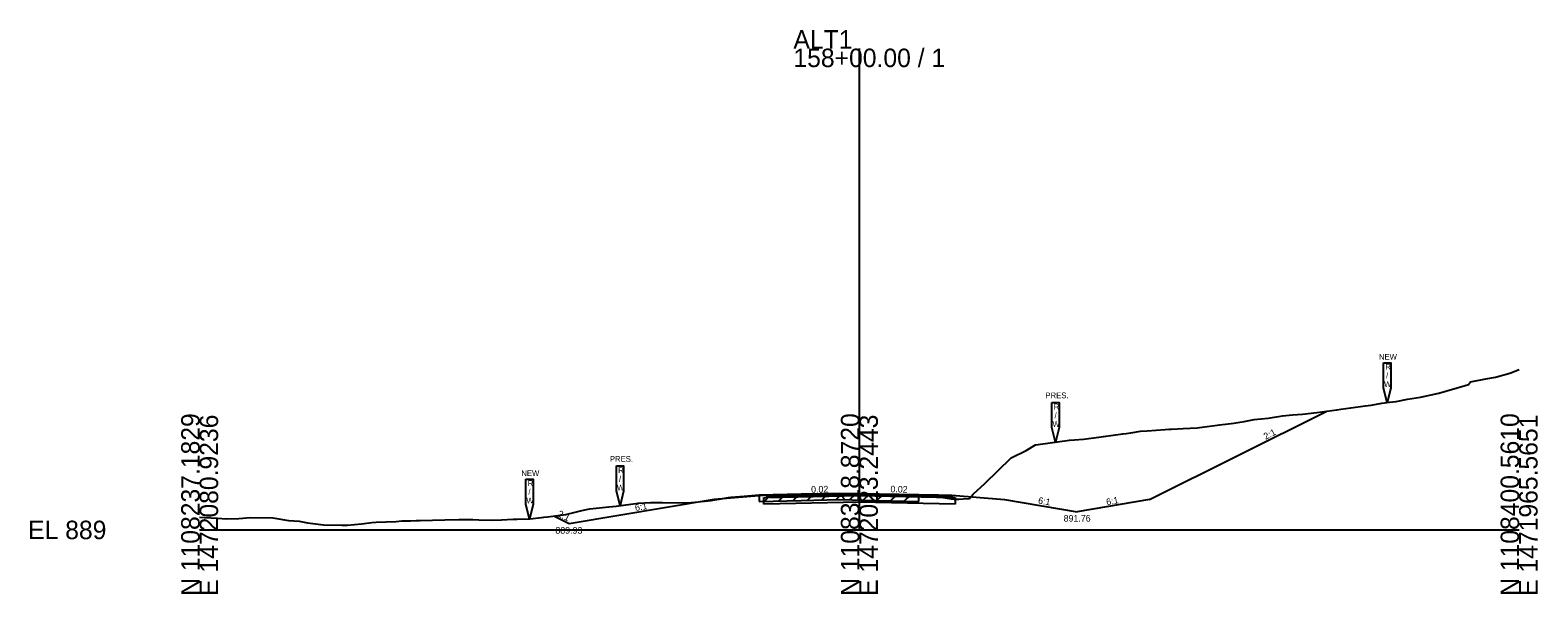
# Model space of a CAD drawing. Extents: x -26 to 2203, y -10 to 19568.
# Drawn here: x 974.3 to 1202.8, y -9.7 to 75.8 of the extents above; entities that cross this region are included whole.
import ezdxf

# ---------------------------------------------------------------- set-up
doc = ezdxf.new("R2010")
doc.units = 0
for name, color, linetype in [('RD_GPK_XS_Cell', 7, 'Continuous'), ('RD_XS_Base', 7, 'Continuous'), ('RD_XS_ExGround', 7, 'Continuous'), ('RD_XS_ExPaveRet', 7, 'Continuous'), ('RD_XS_ExRW', 7, 'Continuous'), ('RD_XS_Greenside', 7, 'Continuous'), ('RD_XS_NewRW', 7, 'Continuous'), ('RD_XS_Pave', 7, 'Continuous'), ('RD_XS_TieSlope', 7, 'Continuous'), ('RD_XS_TX_Slope', 7, 'Continuous')]:
    doc.layers.add(name, color=color, linetype=linetype)

msp = doc.modelspace()

# ---------------------------------------------------------------- linework, layer by layer
at = {"layer": 'RD_GPK_XS_Cell'}
for p, q in [((1100, 0), (1100, 72.98)), ((1000, 0), (1100, 0)), ((1100, 0), (1200, 0))]:
    msp.add_line(p, q, dxfattribs=at)
at = {"layer": 'RD_XS_Base'}
for points in [[(1085.5, 4.93), (1086, 4.94), (1100, 5.22), (1114, 4.94), (1114.5, 4.93)], [(1085.5, 3.93), (1085.5, 4.93)], [(1114.5, 4.93), (1114.5, 3.93)], [(1114.5, 3.93), (1100, 4.22), (1085.5, 3.93)]]:
    msp.add_lwpolyline(points, dxfattribs=at)
at = {"layer": 'RD_XS_ExGround'}
msp.add_lwpolyline([(1000, 1.94), (1000.73, 1.88), (1002.68, 1.79), (1004.06, 1.66), (1005.94, 1.73), (1007.73, 1.89), (1011.09, 1.83), (1011.42, 1.78), (1013.45, 1.42), (1015.08, 1.31), (1016.34, 1.07), (1018.75, 0.79), (1021.54, 0.7), (1022.42, 0.74), (1024.55, 0.94), (1026.1, 1.13), (1026.74, 1.16), (1029.77, 1.28), (1030.67, 1.37), (1031.94, 1.38), (1032.82, 1.42), (1033.44, 1.44), (1037.14, 1.54), (1039.28, 1.6), (1040.79, 1.6), (1041.43, 1.57), (1042.34, 1.51), (1044.46, 1.48), (1045.74, 1.53), (1047.54, 1.61), (1048.13, 1.63), (1050.04, 1.68), (1051.8, 1.86), (1052.19, 1.92), (1052.75, 1.97), (1055.48, 2.33), (1057.95, 2.94), (1058.65, 3.1), (1059.15, 3.19), (1062.03, 3.49), (1063.15, 3.61), (1066.49, 4.07), (1068.35, 4.18), (1069.41, 4.17), (1070.16, 4.18), (1073.84, 4.09), (1074.53, 4.18), (1077.51, 4.46), (1078.02, 4.56), (1078.75, 4.69), (1080.18, 4.92), (1080.55, 4.97), (1082.53, 5.13), (1084.82, 5.31), (1091.16, 5.46), (1097.01, 5.59), (1100, 5.51), (1102.54, 5.45), (1108.96, 5.3), (1110.93, 5.23), (1111.45, 5.14), (1113.89, 4.72), (1114.35, 4.65), (1115.09, 4.65), (1115.75, 4.71), (1116.67, 4.79), (1117.27, 5.43), (1119.01, 7.02), (1123.01, 10.91), (1125.29, 12.04), (1126.69, 12.89), (1127.12, 12.95), (1131.84, 13.63), (1132.6, 13.68), (1133.99, 13.77), (1136.27, 14.06), (1137, 14.16), (1139.94, 14.55), (1140.45, 14.61), (1141.17, 14.73), (1142.6, 14.98), (1143.61, 15.04), (1146.37, 15.22), (1146.91, 15.27), (1147.29, 15.29), (1149.06, 15.4), (1151.21, 15.47), (1151.57, 15.51), (1154.63, 15.92), (1156.77, 16.2), (1157.67, 16.33), (1158.3, 16.45), (1159.82, 16.73), (1161.98, 16.96), (1164.13, 17.29), (1165.65, 17.43), (1167.17, 17.56), (1169.32, 17.8), (1172.37, 18.23), (1172.99, 18.31), (1174.48, 18.51), (1176.67, 18.8), (1177.57, 18.94), (1179.19, 19.22), (1180.34, 19.35), (1181.35, 19.46), (1183.1, 19.84), (1185.07, 20.13), (1187.81, 20.73), (1191.81, 21.91), (1192.31, 22.03), (1192.62, 22.47), (1194.96, 22.9), (1196.42, 23.18), (1198.57, 23.76), (1200, 24.33)], dxfattribs=at)
at = {"layer": 'RD_XS_ExPaveRet'}
for p, q in [((1084.82, 5.31), (1084.82, 4.31)), ((1085.57, 4.33), (1086.59, 5.35)), ((1087.74, 4.38), (1088.77, 5.4)), ((1089.91, 4.43), (1090.94, 5.45)), ((1092.08, 4.48), (1093.11, 5.5)), ((1094.25, 4.53), (1095.28, 5.55)), ((1096.42, 4.58), (1097.43, 5.58)), ((1098.52, 4.55), (1099.5, 5.53)), ((1100.59, 4.5), (1101.57, 5.48)), ((1102.66, 4.45), (1103.64, 5.43)), ((1104.73, 4.4), (1105.71, 5.38)), ((1106.8, 4.35), (1107.78, 5.33)), ((1108.96, 5.3), (1108.96, 4.3)), ((1108.87, 4.3), (1108.96, 4.38))]:
    msp.add_line(p, q, dxfattribs=at)
msp.add_lwpolyline([(1084.82, 4.31), (1091.18, 4.46), (1097, 4.59), (1102.52, 4.45), (1108.96, 4.3)], dxfattribs=at)
at = {"layer": 'RD_XS_ExRW'}
for points in [[(1129.19, 19.34), (1130.29, 19.34), (1130.29, 15.51), (1129.74, 13.32), (1129.19, 15.51)], [(1063.18, 9.7), (1064.27, 9.7), (1064.27, 5.87), (1063.72, 3.68), (1063.18, 5.87)]]:
    msp.add_lwpolyline(points, close=True, dxfattribs=at)
at = {"layer": 'RD_XS_Greenside'}
for points in [[(1078, 4.59), (1056, 0.93)], [(1086, 5.26), (1078, 4.59)], [(1114, 5.26), (1122, 4.59)], [(1122, 4.59), (1133, 2.76)], [(1144, 4.59), (1133, 2.76)]]:
    msp.add_lwpolyline(points, dxfattribs=at)
at = {"layer": 'RD_XS_NewRW'}
for points in [[(1179.45, 25.33), (1180.55, 25.33), (1180.55, 21.5), (1180, 19.32), (1179.45, 21.5)], [(1049.45, 7.69), (1050.55, 7.69), (1050.55, 3.86), (1050, 1.68), (1049.45, 3.86)]]:
    msp.add_lwpolyline(points, close=True, dxfattribs=at)
at = {"layer": 'RD_XS_Pave'}
for points in [[(1086, 5.26), (1088, 5.3), (1100, 5.54), (1112, 5.3), (1114, 5.26)], [(1086, 5.1), (1100, 5.38), (1114, 5.1)], [(1114, 5.1), (1100, 5.38), (1086, 5.1)], [(1086, 5.1), (1086, 5.26)], [(1114, 4.94), (1100, 5.22), (1086, 4.94)], [(1086, 4.94), (1086, 5.1)], [(1114, 5.26), (1114, 5.1)], [(1114, 5.1), (1114, 4.94)]]:
    msp.add_lwpolyline(points, dxfattribs=at)
at = {"layer": 'RD_XS_TieSlope'}
for points in [[(1144, 4.59), (1170.84, 18.01)], [(1056, 0.93), (1053.67, 2.09)]]:
    msp.add_lwpolyline(points, dxfattribs=at)

# ---------------------------------------------------------------- texts
at = {"layer": 'RD_GPK_XS_Cell'}
for s, p in [('ALT1', (1090, 72.98)), ('158+00.00 / 1', (1090, 70.18)), ('EL 889', (974, -1.4))]:
    msp.add_text(s, height=2.8, dxfattribs=at).set_placement(p)
for s, p in [('N 1108237.1829', (1000, -10)), ('E 1472080.9236', (1002.8, -10)), ('N 1108318.8720', (1100, -10)), ('E 1472023.2443', (1102.8, -10)), ('N 1108400.5610', (1200, -10)), ('E 1471965.5651', (1202.8, -10))]:
    msp.add_text(s, height=2.8, rotation=90, dxfattribs=at).set_placement(p)
at = {"layer": 'RD_XS_ExRW'}
for s, p in [('PRES.', (1128.2, 19.96)), ('R', (1129.46, 18.25)), ('W', (1129.27, 15.62)), ('/', (1129.58, 16.93)), ('PRES.', (1062.18, 10.33)), ('R', (1063.44, 8.61)), ('W', (1063.25, 5.98)), ('/', (1063.56, 7.3))]:
    msp.add_text(s, height=0.875, dxfattribs=at).set_placement(p)
at = {"layer": 'RD_XS_NewRW'}
for s, p in [('NEW', (1178.75, 25.81)), ('R', (1179.71, 24.29)), ('/', (1179.83, 22.98)), ('W', (1179.53, 21.67)), ('NEW', (1048.75, 8.17)), ('R', (1049.71, 6.65)), ('W', (1049.53, 4.03)), ('/', (1049.83, 5.34))]:
    msp.add_text(s, height=0.875, dxfattribs=at).set_placement(p)
at = {"layer": 'RD_XS_TX_Slope'}
for s, rotation, p in [('2:1', 26.5651, (1161.58, 13.66)), ('0.02', 1.1458, (1092.69, 5.64)), ('0.02', 358.8542, (1104.7, 5.7)), ('6:1', 350.5358, (1127.04, 4.01)), ('6:1', 10.416, (1137.51, 3.73)), ('2:1', 333.4349, (1054.15, 2.13)), ('6:1', 9.4642, (1066.07, 2.86))]:
    msp.add_text(s, height=1, rotation=rotation, dxfattribs=at).set_placement(p)
for s, p in [('889.93', (1053.92, -0.57)), ('891.76', (1130.96, 1.26))]:
    msp.add_text(s, height=1, dxfattribs=at).set_placement(p)

doc.saveas('drawing.dxf')
